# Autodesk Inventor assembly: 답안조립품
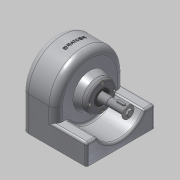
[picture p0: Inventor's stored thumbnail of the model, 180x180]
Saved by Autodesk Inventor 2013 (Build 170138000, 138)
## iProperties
Created: 2015-02
Part Number: 답안조립품
Document SubType Name: Assembly
Designer: Administrator
Author: Administrator
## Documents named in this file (14)
- C:\Users\Administrator\Desktop\450216V1012\답안조립품.iam
- C:\Users\Administrator\Desktop\450216V1012\본체.ipt
- C:\Users\Administrator\Desktop\450216V1012\축커버.ipt
- C:\Users\Administrator\Desktop\450216V1012\오일실.ipt
- C:\Users\Administrator\Desktop\450216V1012\베어링 6001.ipt
- C:\Users\Administrator\Desktop\450216V1012\축.ipt
- C:\Users\Administrator\Desktop\450216V1012\키5x5.ipt
- C:\Users\Administrator\Desktop\450216V1012\키4x4.ipt
- C:\Users\Administrator\Desktop\450216V1012\V-벨트풀리.ipt
- C:\Users\Administrator\Desktop\450216V1012\와샤.ipt
- C:\Users\Administrator\Desktop\450216V1012\스퍼기어.ipt
- C:\Users\Administrator\Desktop\450216V1012\M5x0.8.ipt
- M5x0.8.ipt
- C:\Users\Administrator\Desktop\450216V1012\M3x0.5.ipt
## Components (6 placed, 3 different names)
1. V-벨트풀리:1 — 각도:2, 플러쉬:1
2. M5x0.8:1 — 각도:3
3. M3x0.5:1
4. M3x0.5:2
5. M3x0.5:3
6. M3x0.5:4
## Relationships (3: Angle 2, Flush 1)
- 각도:2 [Angle]: V-벨트풀리:1
- 플러쉬:1 [Flush]: V-벨트풀리:1
- 각도:3 [Angle]: M5x0.8:1
